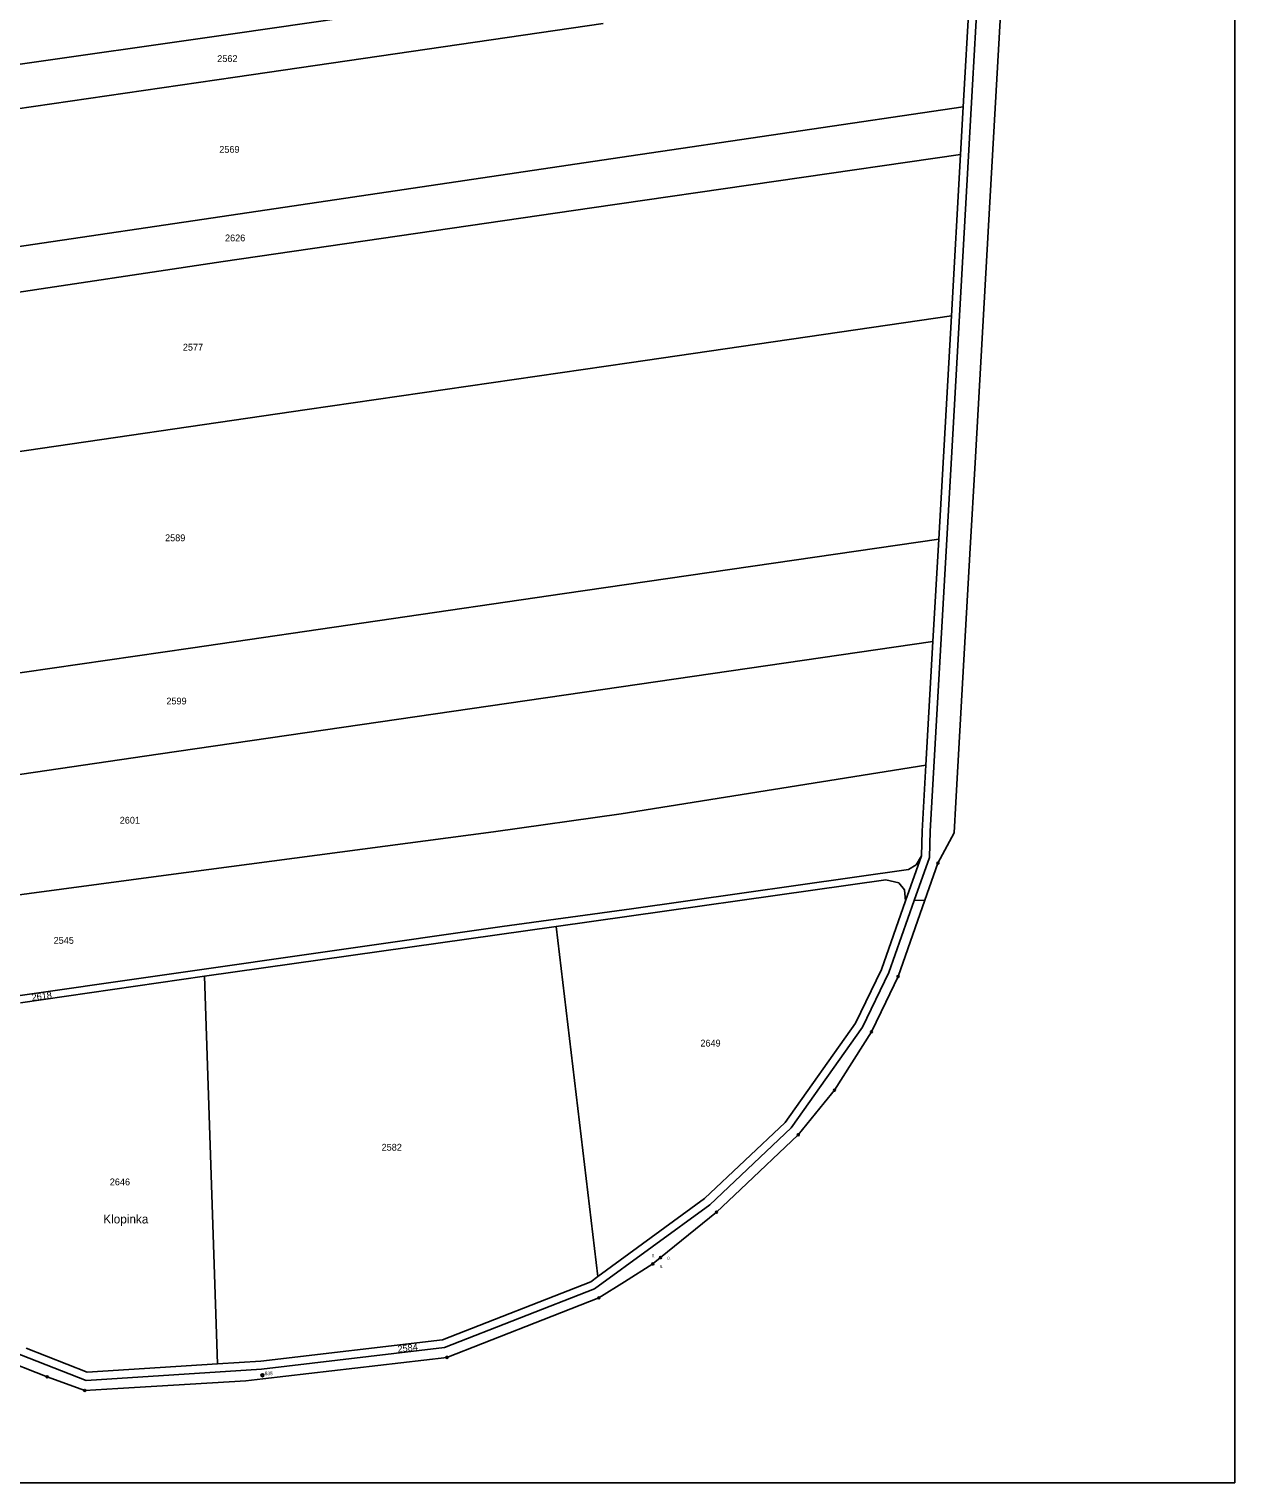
# Model space of a CAD drawing. Extents: x -565355 to -564154, y -1097649 to -1095548.
# Drawn here: x -564757 to -564155, y -1097648 to -1096921 of the extents above; entities that cross this region are included whole.
import ezdxf

# ---------------------------------------------------------------- set-up
doc = ezdxf.new("R2010")
doc.units = 0
for name, color, linetype in [('Vrstva 1', 7, 'Continuous'), ('Vrstva 13', 7, 'Continuous'), ('Vrstva 15', 7, 'Continuous'), ('Vrstva 17', 7, 'Continuous'), ('Vrstva 18', 7, 'Continuous'), ('Vrstva 24', 7, 'Continuous'), ('Vrstva 63', 7, 'Continuous')]:
    doc.layers.add(name, color=color, linetype=linetype)

msp = doc.modelspace()

# ---------------------------------------------------------------- linework, layer by layer
at = {"layer": 'Vrstva 1'}
for p, q in [((-564285.9, -1096948.97), (-564275.31, -1096762.41)), ((-564286.66, -1096891.66), (-564290.54, -1096959.99)), ((-564654.5, -1096923.44), (-564469.95, -1096896.6)), ((-564838.38, -1096949.6), (-564654.5, -1096923.44)), ((-564470.58, -1096918.4), (-564654.51, -1096945.14)), ((-564654.51, -1096945.14), (-564838.44, -1096971.89)), ((-564296.5, -1097135.53), (-564285.9, -1096948.97)), ((-564290.54, -1096959.99), (-564462.25, -1096985.4)), ((-564291.89, -1096983.76), (-564290.54, -1096959.99)), ((-564462.25, -1096985.4), (-564647.5, -1097012.79)), ((-564476.18, -1097010.56), (-564291.89, -1096983.76)), ((-564291.89, -1096983.76), (-564296.48, -1097064.53)), ((-564660.46, -1097037.35), (-564476.18, -1097010.56)), ((-564647.5, -1097012.79), (-564831.67, -1097040.02)), ((-564844.67, -1097064.85), (-564660.46, -1097037.35)), ((-564457.46, -1097087.94), (-564296.48, -1097064.53)), ((-564296.48, -1097064.53), (-564302.81, -1097176.11)), ((-564618.44, -1097111.35), (-564457.46, -1097087.94)), ((-564618.44, -1097111.35), (-564779.43, -1097134.75)), ((-564307.09, -1097322.09), (-564296.5, -1097135.53)), ((-564489.84, -1097203.3), (-564302.81, -1097176.11)), ((-564302.81, -1097176.11), (-564305.71, -1097227.33)), ((-564676.86, -1097230.5), (-564489.84, -1097203.3)), ((-564305.71, -1097227.33), (-564499.36, -1097255.48)), ((-564305.71, -1097227.33), (-564309.21, -1097289.05)), ((-564676.86, -1097230.5), (-564863.89, -1097257.7)), ((-564499.36, -1097255.48), (-564693, -1097283.64)), ((-564886.64, -1097311.8), (-564693, -1097283.64)), ((-564309.21, -1097289.05), (-564461.56, -1097313.31)), ((-564309.21, -1097289.05), (-564311.09, -1097321.97)), ((-564461.56, -1097313.31), (-564525.36, -1097322.32)), ((-564525.36, -1097322.32), (-564690.3, -1097344.26)), ((-564311.45, -1097334.45), (-564311.09, -1097321.97)), ((-564307.47, -1097335.19), (-564307.09, -1097322.09)), ((-564311.45, -1097334.45), (-564319.38, -1097356.9)), ((-564315.07, -1097356.72), (-564307.47, -1097335.19)), ((-564314.1, -1097338.89), (-564311.45, -1097334.45)), ((-564690.3, -1097344.26), (-564855.23, -1097366.19)), ((-564456.37, -1097360.88), (-564317.98, -1097341.16)), ((-564317.98, -1097341.16), (-564314.1, -1097338.89)), ((-564494.08, -1097369.73), (-564329.27, -1097346.3)), ((-564329.27, -1097346.3), (-564322.69, -1097347.91)), ((-564319.93, -1097351.31), (-564322.69, -1097347.91)), ((-564319.38, -1097356.9), (-564319.93, -1097351.31)), ((-564319.38, -1097356.9), (-564331.48, -1097391.18)), ((-564327.78, -1097392.72), (-564315.07, -1097356.72)), ((-564315.07, -1097356.72), (-564309.69, -1097356.49)), ((-564520.96, -1097369.74), (-564456.37, -1097360.88)), ((-564686.26, -1097393.38), (-564520.96, -1097369.74)), ((-564494.08, -1097369.73), (-564669.72, -1097394.5)), ((-564473.12, -1097544.61), (-564494.08, -1097369.73)), ((-564851.57, -1097417.02), (-564686.26, -1097393.38)), ((-564761.7, -1097407.8), (-564669.72, -1097394.5)), ((-564669.72, -1097394.5), (-564663.29, -1097588.36)), ((-564331.48, -1097391.18), (-564344.33, -1097417.94)), ((-564340.88, -1097419.98), (-564327.78, -1097392.72)), ((-564344.33, -1097417.94), (-564379.61, -1097467.64)), ((-564376.57, -1097470.28), (-564340.88, -1097419.98)), ((-564379.61, -1097467.64), (-564419.8, -1097505.71)), ((-564417.23, -1097508.79), (-564376.57, -1097470.28)), ((-564474.79, -1097550.79), (-564417.23, -1097508.79)), ((-564419.8, -1097505.71), (-564473.12, -1097544.61)), ((-564476.73, -1097547.25), (-564550.78, -1097576.23)), ((-564476.73, -1097547.25), (-564473.12, -1097544.61)), ((-564549.8, -1097580.14), (-564474.79, -1097550.79)), ((-564813.84, -1097563.35), (-564728.98, -1097596.54)), ((-564550.78, -1097576.23), (-564641.71, -1097586.9)), ((-564728.35, -1097592.49), (-564758.88, -1097580.52)), ((-564641.35, -1097590.89), (-564549.8, -1097580.14)), ((-564728.98, -1097596.54), (-564641.35, -1097590.89)), ((-564663.29, -1097588.36), (-564728.35, -1097592.49)), ((-564641.71, -1097586.9), (-564663.29, -1097588.36))]:
    msp.add_line(p, q, dxfattribs=at)
at = {"layer": 'Vrstva 13'}
for p, q in [((-564277.71, -1097016.43), (-564269.4, -1096869.98)), ((-564277.71, -1097016.43), (-564284.61, -1097137.94)), ((-564284.61, -1097137.94), (-564287.03, -1097180.53)), ((-564287.03, -1097180.53), (-564291.2, -1097253.99)), ((-564291.2, -1097253.99), (-564294.24, -1097307.55)), ((-564294.24, -1097307.55), (-564295.11, -1097322.88)), ((-564295.11, -1097322.88), (-564303.19, -1097338.08)), ((-564303.19, -1097338.08), (-564309.69, -1097356.49)), ((-564309.69, -1097356.49), (-564323.16, -1097394.64)), ((-564323.16, -1097394.64), (-564329.33, -1097407.49)), ((-564329.33, -1097407.49), (-564336.45, -1097422.31)), ((-564336.45, -1097422.31), (-564354.95, -1097451.51)), ((-564354.95, -1097451.51), (-564360.08, -1097457.84)), ((-564360.08, -1097457.84), (-564372.99, -1097473.77)), ((-564372.99, -1097473.77), (-564401.82, -1097501.07)), ((-564401.82, -1097501.07), (-564413.86, -1097512.48)), ((-564413.86, -1097512.48), (-564441.86, -1097535.21)), ((-564445.75, -1097538.37), (-564459.85, -1097547.25)), ((-564441.86, -1097535.21), (-564445.75, -1097538.37)), ((-564459.85, -1097547.25), (-564472.66, -1097555.32)), ((-564472.66, -1097555.32), (-564495.98, -1097564.45)), ((-564495.98, -1097564.45), (-564530.8, -1097578.07)), ((-564530.8, -1097578.07), (-564548.58, -1097585.03)), ((-564548.58, -1097585.03), (-564640.66, -1097595.84)), ((-564753.94, -1097592.62), (-564767.39, -1097587.26)), ((-564748.43, -1097594.82), (-564753.94, -1097592.62)), ((-564748.43, -1097594.82), (-564729.66, -1097601.58)), ((-564649.06, -1097596.83), (-564713.03, -1097600.6)), ((-564640.66, -1097595.84), (-564649.06, -1097596.83)), ((-564713.03, -1097600.6), (-564729.66, -1097601.58))]:
    msp.add_line(p, q, dxfattribs=at)
at = {"layer": 'Vrstva 24'}
for centre, radius in [((-564303.19, -1097338.08), 0.5), ((-564303.19, -1097338.08), 0.0327), ((-564323.16, -1097394.64), 0.5), ((-564323.16, -1097394.64), 0.0327), ((-564336.45, -1097422.31), 0.5), ((-564336.45, -1097422.31), 0.0327), ((-564354.95, -1097451.51), 0.5), ((-564354.95, -1097451.51), 0.0327), ((-564372.99, -1097473.77), 0.5), ((-564372.99, -1097473.77), 0.0327), ((-564413.86, -1097512.48), 0.5), ((-564413.86, -1097512.48), 0.0327), ((-564441.86, -1097535.21), 0.5), ((-564445.75, -1097538.37), 0.5), ((-564445.75, -1097538.37), 0.0327), ((-564441.86, -1097535.21), 0.0327), ((-564472.66, -1097555.32), 0.5), ((-564472.66, -1097555.32), 0.0327), ((-564548.58, -1097585.03), 0.5), ((-564548.58, -1097585.03), 0.0327), ((-564748.43, -1097594.82), 0.5), ((-564748.43, -1097594.82), 0.0327), ((-564640.82, -1097593.97), 0.75), ((-564640.82, -1097593.97), 0.0327), ((-564729.66, -1097601.58), 0.5), ((-564729.66, -1097601.58), 0.0327)]:
    msp.add_circle(centre, radius, dxfattribs=at)
at = {"layer": 'Vrstva 63'}
for p, q in [((-564154.77, -1095547.8), (-564154.77, -1097647.8)), ((-564154.77, -1097647.8), (-565342.77, -1097647.8))]:
    msp.add_line(p, q, dxfattribs=at)

# ---------------------------------------------------------------- texts
at = {"layer": 'Vrstva 15'}
for s, height, p in [('Klopinka', 4.4, (-564720.39, -1097518.11)), ('T.', 1.4, (-564446.21, -1097535.02)), ('Ú.', 1.4, (-564438.66, -1097536.2)), ('S.', 1.4, (-564442.32, -1097540.34))]:
    msp.add_text(s, height=height, dxfattribs=at).set_placement(p)
at = {"layer": 'Vrstva 17'}
msp.add_text('535', height=1.7, dxfattribs=at).set_placement((-564639.63, -1097593.96))
at = {"layer": 'Vrstva 18'}
for s, p in [('2562', (-564663.42, -1096937.61)), ('2569', (-564662.39, -1096983)), ('2626', (-564659.52, -1097027.24)), ('2577', (-564680.6, -1097081.84)), ('2589', (-564689.48, -1097177.13)), ('2599', (-564688.82, -1097258.7)), ('2601', (-564712.14, -1097318.27)), ('2545', (-564745.19, -1097378.33)), ('2649', (-564421.94, -1097429.7)), ('2582', (-564581.26, -1097481.73)), ('2646', (-564717.11, -1097499.05))]:
    msp.add_text(s, height=3.4, dxfattribs=at).set_placement(p)
for s, rotation, p in [('2618', 7.2, (-564755.96, -1097406.85)), ('2584', 6.3, (-564573.11, -1097582.62))]:
    msp.add_text(s, height=3.4, rotation=rotation, dxfattribs=at).set_placement(p)

doc.saveas('drawing.dxf')
